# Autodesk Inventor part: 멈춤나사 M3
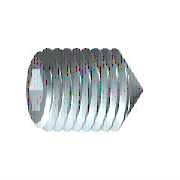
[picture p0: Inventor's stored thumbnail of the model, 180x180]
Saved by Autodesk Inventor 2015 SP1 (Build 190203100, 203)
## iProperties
IsCustomPart: 1
Created: 2012-02
Part Number: 멈춤나사 M3
Material: 강철, 연강
Description: 6각 소켓 머리 없는 멈춤 나사
Document SubType Name: Modeling
Standard: KS B 1028
Designer: test
Standards Organization: KS
Language: ko-KR
Size Designation: 원추점 M3x8
Categories: <MemberInstance><Categories><Category DisplayName="조임쇠" InternalName="e4da775c-781d-43d5-af7c-5136215cf5a6" Mnemonic="FSTN"><Category DisplayName="볼트" InternalN
Density: 1 g/cm^3
Appearance: 강철
Author: test
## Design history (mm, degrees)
sketch "스케치1"
  geometry: L1 (0, 0)-(5.5, 0); L2 (8, 0.866)-(8, 1.5); L3 (8, 1.5)-(0, 1.5); L4 (8, 0.866)-(6, 0.866); L5 (6, 0.866)-(5.5, 0); L6 (0, -0.3)-(0, 1.8) reference; L7 (0, 1.5)-(0, 0)
  constraints: 13 end point, 3 parallel, 1 collinear, 1 perpendicular, 1 point on line
  dimensions: "d0" = 2 distance of L2.start L4.end (= INTI); "d1" = 60 deg angle of L5 L1; "d2" = 3 diameter of L3 L1 (= NND); "d3" = 1.73205 diameter of L4 L1 (= 1.1547 x SW); "d5" = 8 distance from line of L2 L3.end (= NLG)
revolve "본체" sketch "스케치1" stored, may be unused: angle "d6" = 90 deg
sketch "스케치2"
  geometry: L1 (-0.433, 0.75)-(0.433, 0.75); L2 (0.433, 0.75)-(0.866, 0); L3 (0.866, 0)-(0.433, -0.75); L4 (0.433, -0.75)-(-0.433, -0.75); L5 (-0.433, -0.75)-(-0.866, 0); L6 (-0.866, 0)-(-0.433, 0.75); 3 further points
  constraints: 12 end point, 1 coincident, 1 horizontal, 13 other
extrude "슬롯" join sketch "스케치2" taper "d7" = 0 deg; stored distance "d21" = 10
workaxis "Work Axis1"
workplane "Work Plane1"
sketch "스케치4"
  geometry: L1 (0, 0.15)-(-1.35, 1.5) reference; L2 (0, -0.15)-(-1.35, -1.5) reference; L3 (-1.35, -1.5)-(0.15, 0); L4 (-1.35, 1.5)-(0.15, 0); 2 further points
  constraints: 4 end point, 1 coincident, 1 collinear, 1 horizontal alignment
body "Solid1"
feature "스레드" dims "d12" = 8 (= NLG), "d13" = 0
chamfer "모따기1" distance "d8" = 1.35 (computed from NND, SPD, FAWI); stored, may be unused: angle "d9" = 45 deg (= FAWI), second distance "d34" = 1.35 (computed from NND, SPD, FAWI)
chamfer "모따기2" distance "d10" = 0.30673 (= -0.5 x GD1 + 0.5 x NND); stored, may be unused: angle "d11" = 45 deg (= FAWI), second distance "d35" = 0.30673 (= -0.5 x GD1 + 0.5 x NND)
other parameters: "NND" = 3 [user parameter; used in 5 equation terms], "NLG" = 8 [user parameter; used in 2 equation terms], "INTI" = 2 [user parameter; used in 1 equation term], "FAWI" = 45 deg [user parameter; used in 4 equation terms], "SW" = 1.5 [user parameter; used in 2 equation terms], "GD1" = 2.38655 (= THREADDIA - 1.2269 x PTC) [user parameter; used in 2 equation terms], "d4" = 0, "FAWI1" = 45 deg [user parameter], "SPD" = 0.3 [user parameter; used in 2 equation terms], "d36" = 0, "d37" = 0, "GUL" = 0.30673 (= 0.61345 x PTC) [user parameter], "TOA" = 30 deg [user parameter], "THREADDIA" = 3 [user parameter; used in 1 equation term], "PTC" = 0.5 [user parameter; used in 4 equation terms], "GAL" = 0.30673 (= 0.61345 x PTC) [user parameter], "E0" = 1.7325 (= 1.155 x SW) [user parameter]
